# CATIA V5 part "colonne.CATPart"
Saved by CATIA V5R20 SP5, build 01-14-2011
Part number: colonneS
Publications: "Droite.1", "Point.1", "Point.2"
Bounding box of the stored display mesh (mm): x 0 to 0, y 0 to 200, z 0 to 1000
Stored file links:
  U:\think motion\fin\colonne.CATPart
  U:\think motion\fin\squelette.CATProduct
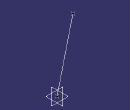
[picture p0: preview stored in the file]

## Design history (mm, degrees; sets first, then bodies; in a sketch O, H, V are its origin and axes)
Set1
  Point1: linked copy from another document
  Point2: linked copy from another document
Set2
  Line1: type PtPt, FirstPoint Point1, SecondPoint Point2
Body1 (main body)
